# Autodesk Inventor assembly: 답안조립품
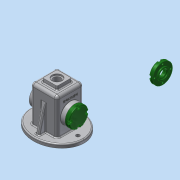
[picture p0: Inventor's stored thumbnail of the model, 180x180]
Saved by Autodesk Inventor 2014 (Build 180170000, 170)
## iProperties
Created: 2017-07
Part Number: 답안조립품
Document SubType Name: Assembly
Designer: 702-11
Author: 702-11
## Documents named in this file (4)
- C:\Users\702-11\Desktop\470708V1021\답안조립품.iam
- C:\Users\702-11\Desktop\470708V1021\본체.ipt
- C:\Users\702-11\Desktop\470708V1021\앞커버.ipt
- C:\Users\702-11\Desktop\470708V1021\뒤커버.ipt
